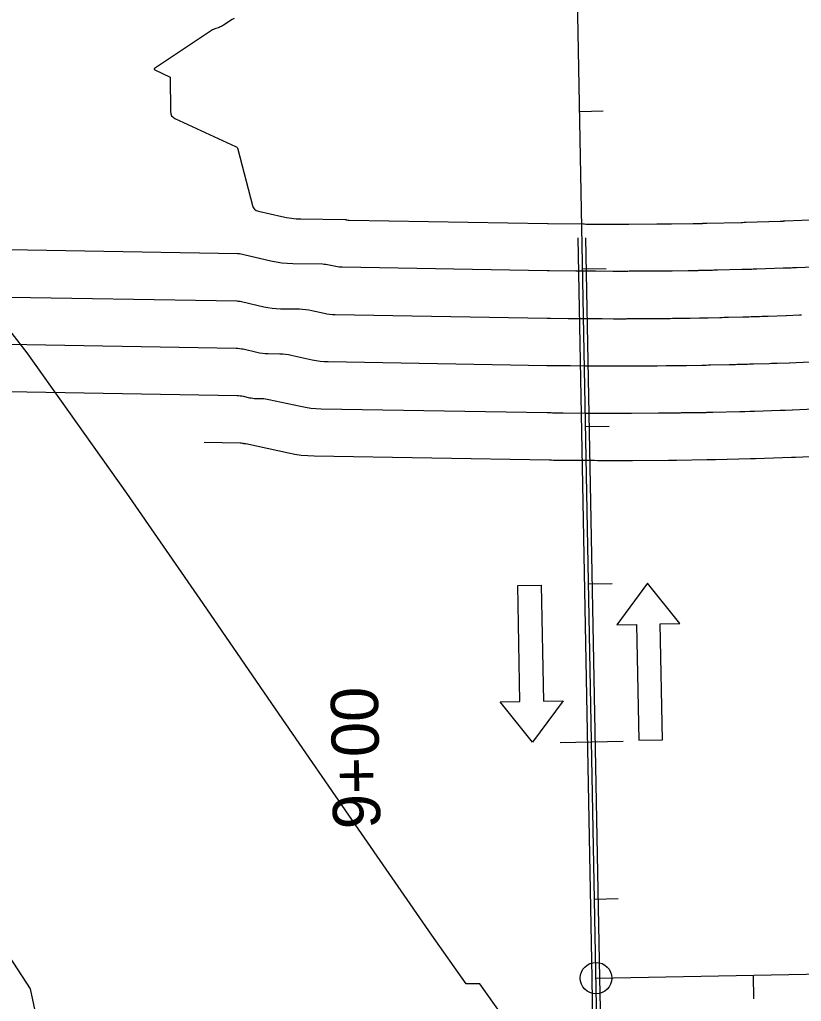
# Model space of a CAD drawing. Extents: x 1710723 to 1713003, y 548603 to 551142.
# Drawn here: x 1711666.3 to 1711765.6, y 549079.5 to 549204.1 of the extents above; entities that cross this region are included whole.
import ezdxf

# ---------------------------------------------------------------- set-up
doc = ezdxf.new("R2010")
doc.units = 0
for name, color, linetype in [('R_Contours', 7, 'Continuous'), ('R_Horz Alg', 7, 'Continuous'), ('R_Horz Alg Annot', 7, 'Continuous'), ('R_MOT', 7, 'Continuous'), ('R_No Plot', 7, 'Continuous'), ('R_Striping', 7, 'Continuous')]:
    doc.layers.add(name, color=color, linetype=linetype)

msp = doc.modelspace()

# ---------------------------------------------------------------- linework, layer by layer
at = {"layer": 'R_Contours'}
for points in [[(1711693.57, 549204.24), (1711693.33, 549204.11), (1711692.21, 549203.4), (1711692.08, 549203.32), (1711691.95, 549203.25), (1711691.81, 549203.19), (1711691.67, 549203.13), (1711691.1, 549202.93), (1711690.96, 549202.87), (1711690.82, 549202.81), (1711690.69, 549202.74), (1711690.56, 549202.66), (1711683.47, 549197.9), (1711683.42, 549197.85), (1711683.4, 549197.8), (1711683.42, 549197.76), (1711683.49, 549197.72), (1711685.43, 549196.82), (1711685.44, 549196.82), (1711685.44, 549196.82), (1711685.44, 549196.81), (1711685.44, 549196.81), (1711685.49, 549192.43), (1711685.53, 549192.15), (1711685.63, 549191.91), (1711685.81, 549191.71), (1711686.05, 549191.56), (1711693.75, 549188.02), (1711693.86, 549187.96), (1711693.94, 549187.88), (1711694, 549187.79), (1711694.04, 549187.68), (1711695.89, 549180.53), (1711696, 549180.26), (1711696.16, 549180.05), (1711696.37, 549179.9), (1711696.64, 549179.8), (1711699.63, 549179.11), (1711700.23, 549178.99), (1711700.83, 549178.9), (1711701.44, 549178.84), (1711702.05, 549178.82), (1711707.67, 549178.73), (1711707.71, 549178.72), (1711707.75, 549178.72), (1711707.8, 549178.72), (1711707.84, 549178.71), (1711708, 549178.67), (1711708.04, 549178.66), (1711708.08, 549178.66), (1711708.11, 549178.65), (1711708.15, 549178.65), (1711733.35, 549178.22), (1711733.38, 549178.22), (1711733.42, 549178.22), (1711737.9, 549178.17), (1711737.98, 549178.17), (1711738.06, 549178.17), (1711738.25, 549178.16), (1711738.28, 549178.16), (1711738.31, 549178.16), (1711738.33, 549178.16), (1711738.36, 549178.16), (1711738.5, 549178.16), (1711738.58, 549178.16), (1711741.56, 549178.15), (1711741.61, 549178.15), (1711741.71, 549178.15), (1711741.73, 549178.15), (1711743.14, 549178.15), (1711743.19, 549178.15), (1711743.23, 549178.15), (1711743.28, 549178.15), (1711743.32, 549178.15), (1711743.49, 549178.15), (1711743.58, 549178.15), (1711743.67, 549178.15), (1711747.21, 549178.18), (1711747.69, 549178.18), (1711748.16, 549178.18), (1711748.63, 549178.19), (1711749.1, 549178.2), (1711751.85, 549178.23), (1711751.92, 549178.23), (1711752, 549178.24), (1711752.16, 549178.24), (1711752.2, 549178.24), (1711752.24, 549178.24), (1711752.28, 549178.24), (1711752.32, 549178.24), (1711753, 549178.25), (1711753.07, 549178.26), (1711753.1, 549178.26), (1711753.37, 549178.26), (1711753.47, 549178.26), (1711753.57, 549178.27), (1711757.91, 549178.37), (1711757.96, 549178.37), (1711758.01, 549178.37), (1711758.06, 549178.37), (1711758.11, 549178.37), (1711758.31, 549178.38), (1711758.36, 549178.38), (1711758.41, 549178.39), (1711758.47, 549178.39), (1711758.52, 549178.39), (1711762.89, 549178.53), (1711762.95, 549178.53), (1711763.26, 549178.54), (1711763.31, 549178.55), (1711763.36, 549178.55), (1711763.42, 549178.55), (1711763.47, 549178.55), (1711767.77, 549178.73)], [(1711768.22, 549172.74), (1711764.95, 549172.61), (1711764.78, 549172.6), (1711764.62, 549172.6), (1711764.46, 549172.59), (1711764.29, 549172.58), (1711763.32, 549172.54), (1711763.27, 549172.54), (1711759.93, 549172.43), (1711759.77, 549172.43), (1711759.61, 549172.42), (1711759.45, 549172.42), (1711759.29, 549172.41), (1711758.66, 549172.39), (1711758.5, 549172.39), (1711758.34, 549172.38), (1711758.18, 549172.38), (1711758.02, 549172.37), (1711754.94, 549172.3), (1711754.78, 549172.3), (1711754.62, 549172.29), (1711754.47, 549172.29), (1711754.31, 549172.28), (1711753.41, 549172.26), (1711753.36, 549172.26), (1711753.3, 549172.26), (1711753.17, 549172.26), (1711753.09, 549172.26), (1711752.67, 549172.25), (1711752.59, 549172.25), (1711752.51, 549172.25), (1711752.43, 549172.24), (1711752.35, 549172.24), (1711751.73, 549172.23), (1711751.6, 549172.23), (1711751.47, 549172.23), (1711751.34, 549172.23), (1711751.21, 549172.23), (1711749.15, 549172.2), (1711748.77, 549172.19), (1711748.38, 549172.19), (1711747.99, 549172.18), (1711747.61, 549172.18), (1711744.94, 549172.16), (1711744.78, 549172.16), (1711744.63, 549172.16), (1711744.48, 549172.16), (1711744.32, 549172.16), (1711743.71, 549172.16), (1711743.56, 549172.15), (1711743.4, 549172.15), (1711743.25, 549172.15), (1711743.1, 549172.15), (1711742.25, 549172.15), (1711742.2, 549172.15), (1711742.15, 549172.15), (1711742.1, 549172.15), (1711742.05, 549172.15), (1711741.85, 549172.15), (1711741.8, 549172.15), (1711741.75, 549172.15), (1711741.7, 549172.15), (1711741.64, 549172.15), (1711739.43, 549172.16), (1711739.33, 549172.16), (1711739.23, 549172.16), (1711739.13, 549172.16), (1711739.03, 549172.16), (1711738.63, 549172.16), (1711738.53, 549172.16), (1711738.43, 549172.16), (1711738.33, 549172.17), (1711738.23, 549172.17), (1711737.53, 549172.17), (1711737.38, 549172.17), (1711737.23, 549172.18), (1711737.08, 549172.18), (1711736.93, 549172.18), (1711733.58, 549172.22), (1711733.52, 549172.22), (1711733.45, 549172.22), (1711733.39, 549172.22), (1711733.32, 549172.22), (1711707.27, 549172.67), (1711707.07, 549172.68), (1711706.88, 549172.7), (1711706.69, 549172.72), (1711706.49, 549172.76), (1711705.62, 549172.95), (1711705.41, 549172.99), (1711705.2, 549173.02), (1711704.99, 549173.04), (1711704.78, 549173.05), (1711701, 549173.11), (1711700.3, 549173.14), (1711699.61, 549173.21), (1711698.92, 549173.31), (1711698.23, 549173.45), (1711694.26, 549174.36), (1711694.2, 549174.38), (1711694.13, 549174.39), (1711694.06, 549174.39), (1711693.99, 549174.4), (1711662.46, 549174.94)], [(1711662.42, 549168.94), (1711693.91, 549168.4), (1711694.05, 549168.39), (1711694.2, 549168.38), (1711694.34, 549168.36), (1711694.48, 549168.33), (1711697.33, 549167.67), (1711697.85, 549167.57), (1711698.38, 549167.49), (1711698.91, 549167.44), (1711699.44, 549167.41), (1711701.88, 549167.38), (1711702.26, 549167.36), (1711702.65, 549167.32), (1711703.03, 549167.27), (1711703.41, 549167.2), (1711704.98, 549166.85), (1711705.33, 549166.78), (1711705.68, 549166.73), (1711706.03, 549166.7), (1711706.39, 549166.69), (1711733.29, 549166.22), (1711733.41, 549166.22), (1711733.52, 549166.22), (1711733.63, 549166.22), (1711733.74, 549166.22), (1711735.97, 549166.19), (1711736.22, 549166.19), (1711736.48, 549166.18), (1711736.74, 549166.18), (1711737, 549166.18), (1711738.2, 549166.17), (1711738.37, 549166.17), (1711738.55, 549166.17), (1711738.72, 549166.16), (1711738.89, 549166.16), (1711739.59, 549166.16), (1711739.76, 549166.16), (1711739.93, 549166.16), (1711740.1, 549166.16), (1711740.28, 549166.16), (1711741.73, 549166.15), (1711741.81, 549166.15), (1711741.9, 549166.15), (1711741.99, 549166.15), (1711742.07, 549166.15), (1711742.42, 549166.15), (1711742.51, 549166.15), (1711742.6, 549166.15), (1711742.68, 549166.15), (1711742.77, 549166.15), (1711743.33, 549166.15), (1711743.45, 549166.16), (1711743.57, 549166.16), (1711743.7, 549166.16), (1711743.82, 549166.16), (1711745.15, 549166.17), (1711745.41, 549166.17), (1711745.68, 549166.17), (1711745.94, 549166.17), (1711746.2, 549166.17), (1711748, 549166.19), (1711748.3, 549166.19), (1711748.6, 549166.19), (1711748.9, 549166.19), (1711749.21, 549166.2), (1711750.57, 549166.22), (1711750.79, 549166.22), (1711751.01, 549166.22), (1711751.23, 549166.23), (1711751.45, 549166.23), (1711752.65, 549166.25), (1711752.71, 549166.25), (1711752.78, 549166.25), (1711752.84, 549166.25), (1711752.9, 549166.25), (1711753.18, 549166.26), (1711753.27, 549166.26), (1711753.36, 549166.26), (1711753.54, 549166.26), (1711753.59, 549166.27), (1711753.63, 549166.27), (1711753.68, 549166.27), (1711753.72, 549166.27), (1711755.24, 549166.31), (1711755.51, 549166.31), (1711755.78, 549166.32), (1711756.04, 549166.33), (1711756.31, 549166.33), (1711758.13, 549166.38), (1711758.4, 549166.38), (1711758.66, 549166.39), (1711758.93, 549166.4), (1711759.2, 549166.41), (1711760.27, 549166.44), (1711760.54, 549166.45), (1711760.81, 549166.46), (1711761.08, 549166.47), (1711761.35, 549166.48), (1711763.65, 549166.55), (1711763.7, 549166.55), (1711765.33, 549166.62), (1711765.6, 549166.63)], [(1711662.38, 549162.94), (1711693.83, 549162.4), (1711694.05, 549162.39), (1711694.26, 549162.37), (1711694.48, 549162.34), (1711694.69, 549162.3), (1711696.43, 549161.9), (1711696.79, 549161.82), (1711697.15, 549161.77), (1711697.52, 549161.73), (1711697.88, 549161.72), (1711699.36, 549161.69), (1711699.73, 549161.68), (1711700.1, 549161.65), (1711700.46, 549161.59), (1711700.82, 549161.52), (1711703.48, 549160.94), (1711703.98, 549160.84), (1711704.48, 549160.77), (1711704.99, 549160.72), (1711705.5, 549160.7), (1711733.27, 549160.22), (1711733.43, 549160.22), (1711733.59, 549160.22), (1711733.75, 549160.22), (1711733.91, 549160.21), (1711735.2, 549160.2), (1711735.47, 549160.2), (1711735.73, 549160.19), (1711736, 549160.19), (1711736.27, 549160.19), (1711738.17, 549160.17), (1711738.42, 549160.17), (1711738.66, 549160.17), (1711738.91, 549160.16), (1711739.16, 549160.16), (1711740.28, 549160.16), (1711740.46, 549160.16), (1711740.63, 549160.16), (1711740.81, 549160.16), (1711740.99, 549160.16), (1711741.81, 549160.16), (1711741.93, 549160.16), (1711742.05, 549160.16), (1711742.18, 549160.16), (1711742.3, 549160.16), (1711742.87, 549160.16), (1711742.95, 549160.16), (1711743.04, 549160.16), (1711743.13, 549160.16), (1711743.22, 549160.16), (1711743.57, 549160.16), (1711743.66, 549160.16), (1711743.75, 549160.16), (1711743.83, 549160.16), (1711743.92, 549160.16), (1711746.2, 549160.18), (1711746.46, 549160.18), (1711746.73, 549160.18), (1711746.99, 549160.18), (1711747.25, 549160.18), (1711748.39, 549160.19), (1711748.61, 549160.19), (1711748.83, 549160.19), (1711749.04, 549160.2), (1711749.26, 549160.2), (1711750.13, 549160.21), (1711750.34, 549160.21), (1711750.56, 549160.22), (1711750.77, 549160.22), (1711750.99, 549160.22), (1711752.95, 549160.25), (1711753, 549160.26), (1711753.04, 549160.26), (1711753.09, 549160.26), (1711753.13, 549160.26), (1711753.31, 549160.26), (1711753.4, 549160.26), (1711753.49, 549160.26), (1711753.78, 549160.27), (1711753.85, 549160.27), (1711753.91, 549160.27), (1711753.97, 549160.27), (1711754.04, 549160.28), (1711756.41, 549160.34), (1711756.67, 549160.34), (1711756.93, 549160.35), (1711757.19, 549160.35), (1711757.44, 549160.36), (1711758.48, 549160.38), (1711758.73, 549160.39), (1711758.99, 549160.4), (1711759.25, 549160.41), (1711759.51, 549160.41), (1711761.5, 549160.48), (1711761.76, 549160.49), (1711762.01, 549160.5), (1711762.26, 549160.51), (1711762.51, 549160.51), (1711764.03, 549160.56), (1711764.08, 549160.56), (1711766.63, 549160.67)], [(1711662.34, 549156.95), (1711693.93, 549156.4), (1711694.13, 549156.39), (1711694.33, 549156.37), (1711694.53, 549156.34), (1711694.73, 549156.3), (1711695.52, 549156.12), (1711695.72, 549156.08), (1711695.92, 549156.05), (1711696.12, 549156.03), (1711696.33, 549156.02), (1711697.14, 549156.01), (1711697.34, 549156), (1711697.55, 549155.98), (1711697.75, 549155.95), (1711697.95, 549155.91), (1711701.97, 549155.03), (1711702.62, 549154.9), (1711703.29, 549154.81), (1711703.95, 549154.75), (1711704.62, 549154.72), (1711733.32, 549154.22), (1711733.49, 549154.22), (1711733.65, 549154.22), (1711733.82, 549154.22), (1711733.99, 549154.21), (1711734.65, 549154.21), (1711734.82, 549154.2), (1711734.99, 549154.2), (1711735.15, 549154.2), (1711735.32, 549154.2), (1711738.15, 549154.17), (1711738.47, 549154.17), (1711738.78, 549154.17), (1711739.1, 549154.17), (1711739.42, 549154.16), (1711741.12, 549154.16), (1711741.23, 549154.16), (1711741.34, 549154.16), (1711741.45, 549154.16), (1711741.55, 549154.16), (1711741.99, 549154.16), (1711742.1, 549154.16), (1711742.21, 549154.16), (1711742.32, 549154.16), (1711742.43, 549154.16), (1711743.38, 549154.16), (1711743.43, 549154.16), (1711743.49, 549154.16), (1711743.54, 549154.16), (1711743.59, 549154.16), (1711743.81, 549154.16), (1711743.86, 549154.16), (1711743.92, 549154.16), (1711743.97, 549154.16), (1711744.02, 549154.16), (1711747.45, 549154.19), (1711747.61, 549154.19), (1711747.77, 549154.19), (1711747.93, 549154.19), (1711748.09, 549154.19), (1711748.79, 549154.19), (1711748.92, 549154.2), (1711749.05, 549154.2), (1711749.18, 549154.2), (1711749.31, 549154.2), (1711749.84, 549154.21), (1711749.97, 549154.21), (1711750.1, 549154.21), (1711750.23, 549154.21), (1711750.37, 549154.22), (1711753.26, 549154.26), (1711753.31, 549154.26), (1711753.36, 549154.26), (1711753.5, 549154.26), (1711753.58, 549154.27), (1711754.02, 549154.27), (1711754.1, 549154.28), (1711754.18, 549154.28), (1711754.27, 549154.28), (1711754.35, 549154.28), (1711757.77, 549154.37), (1711757.92, 549154.37), (1711758.08, 549154.38), (1711758.23, 549154.38), (1711758.39, 549154.38), (1711759.01, 549154.4), (1711759.16, 549154.4), (1711759.32, 549154.41), (1711759.47, 549154.41), (1711759.63, 549154.42), (1711762.9, 549154.53), (1711763.06, 549154.53), (1711763.21, 549154.54), (1711763.36, 549154.54), (1711763.51, 549154.55), (1711764.4, 549154.57), (1711764.42, 549154.57), (1711764.46, 549154.58), (1711768.09, 549154.73)], [(1711689.77, 549150.47), (1711694.32, 549150.4), (1711694.36, 549150.39), (1711694.4, 549150.39), (1711694.44, 549150.38), (1711694.47, 549150.38), (1711694.62, 549150.34), (1711694.66, 549150.34), (1711694.7, 549150.33), (1711694.73, 549150.33), (1711694.77, 549150.32), (1711694.92, 549150.32), (1711694.96, 549150.32), (1711695, 549150.32), (1711695.03, 549150.31), (1711695.07, 549150.31), (1711700.46, 549149.12), (1711701.27, 549148.96), (1711702.09, 549148.84), (1711702.91, 549148.77), (1711703.74, 549148.73), (1711733.59, 549148.22), (1711733.66, 549148.22), (1711733.72, 549148.22), (1711733.79, 549148.22), (1711733.85, 549148.22), (1711734.11, 549148.21), (1711734.17, 549148.21), (1711734.24, 549148.21), (1711734.3, 549148.21), (1711734.37, 549148.21), (1711738.12, 549148.17), (1711738.51, 549148.17), (1711738.9, 549148.17), (1711739.3, 549148.17), (1711739.69, 549148.16), (1711741.96, 549148.16), (1711742.04, 549148.16), (1711742.12, 549148.16), (1711742.28, 549148.16), (1711742.32, 549148.16), (1711742.36, 549148.16), (1711742.4, 549148.16), (1711742.44, 549148.16), (1711743.89, 549148.16), (1711743.97, 549148.16), (1711744.05, 549148.16), (1711744.09, 549148.16), (1711744.13, 549148.16), (1711748.71, 549148.2), (1711748.76, 549148.2), (1711748.82, 549148.2), (1711748.88, 549148.2), (1711748.93, 549148.2), (1711749.18, 549148.2), (1711749.23, 549148.2), (1711749.27, 549148.2), (1711749.32, 549148.2), (1711749.37, 549148.2), (1711749.55, 549148.2), (1711749.65, 549148.2), (1711749.74, 549148.21), (1711753.56, 549148.27), (1711753.59, 549148.27), (1711753.67, 549148.27), (1711754.26, 549148.28), (1711754.36, 549148.28), (1711754.46, 549148.28), (1711754.56, 549148.29), (1711754.66, 549148.29), (1711759.13, 549148.4), (1711759.18, 549148.4), (1711759.23, 549148.4), (1711759.28, 549148.4), (1711759.34, 549148.41), (1711759.54, 549148.41), (1711759.6, 549148.41), (1711759.65, 549148.41), (1711759.7, 549148.41), (1711759.75, 549148.42), (1711764.31, 549148.57), (1711764.4, 549148.57), (1711764.5, 549148.58), (1711764.78, 549148.59), (1711764.8, 549148.59), (1711764.83, 549148.59), (1711769.56, 549148.79)]]:
    msp.add_lwpolyline(points, dxfattribs=at)
at = {"layer": 'R_Horz Alg'}
for p, q in [((1711741.76, 548962.46), (1711737.05, 549212.41)), ((1711739.5, 549082.44), (1711789.16, 549083.37))]:
    msp.add_line(p, q, dxfattribs=at)
at = {"layer": 'R_Horz Alg Annot'}
for points in [[(1711740.43, 549192.47), (1711737.43, 549192.42)], [(1711740.81, 549172.48), (1711737.81, 549172.42)], [(1711741.18, 549152.48), (1711738.18, 549152.43)], [(1711741.56, 549132.49), (1711738.56, 549132.43)], [(1711734.94, 549112.36), (1711742.94, 549112.51)], [(1711742.31, 549092.49), (1711739.31, 549092.44)], [(1711759.55, 549079.82), (1711759.5, 549082.81)]]:
    msp.add_lwpolyline(points, dxfattribs=at)
msp.add_circle((1711739.5, 549082.44), 2, dxfattribs=at)
at = {"layer": 'R_MOT'}
for points in [[(1711808.51, 549014.46), (1711797.83, 549015.34), (1711780.72, 549024.22), (1711764.61, 549034.78), (1711754.93, 549047.27), (1711743.56, 549057.03), (1711737.29, 549064.07), (1711724.77, 549081.73), (1711723.01, 549081.72), (1711718.65, 549087.89), (1711708.97, 549101.92), (1711699.3, 549115.95), (1711689.62, 549129.98), (1711679.95, 549144.01), (1711667.27, 549161.8), (1711663.44, 549166.72)], [(1711633.24, 549130.45), (1711648.31, 549110.73), (1711654.76, 549100.85), (1711661.21, 549090.97), (1711667.66, 549081.09), (1711669.8, 549071.12), (1711670.82, 549061.14), (1711671.85, 549051.16), (1711672.88, 549041.18), (1711673.91, 549031.19), (1711688.03, 549012.49)]]:
    msp.add_lwpolyline(points, dxfattribs=at)
for points in [[(1711735.34, 549117.65), (1711731.44, 549112.39), (1711727.34, 549117.5), (1711729.84, 549117.55), (1711729.56, 549132.26), (1711732.56, 549132.32), (1711732.84, 549117.61)], [(1711750.16, 549127.45), (1711746.06, 549132.57), (1711742.16, 549127.3), (1711744.66, 549127.35), (1711744.93, 549112.64), (1711747.93, 549112.7), (1711747.66, 549127.41)]]:
    msp.add_lwpolyline(points, close=True, dxfattribs=at)
at = {"layer": 'R_No Plot'}
msp.add_lwpolyline([(1711869.98, 549020.25), (1711864.58, 549010.42), (1711860.69, 549005.72), (1711855.6, 549004.99), (1711831.16, 549007.62), (1711823.52, 549009.4), (1711808.51, 549014.46), (1711797.83, 549015.34), (1711780.72, 549024.22), (1711764.61, 549034.78), (1711754.93, 549047.27), (1711743.56, 549057.03), (1711737.29, 549064.07), (1711724.77, 549081.73), (1711723.01, 549081.72), (1711718.65, 549087.89), (1711708.97, 549101.92), (1711699.3, 549115.95), (1711689.62, 549129.98), (1711679.95, 549144.01), (1711667.27, 549161.8), (1711663.44, 549166.72)], dxfattribs=at)
at = {"layer": 'R_Striping'}
for p, q in [((1711739, 549082.43), (1711737.23, 549176.42)), ((1711740, 549082.45), (1711738.23, 549176.43)), ((1711739.6, 549050.42), (1711739, 549082.43)), ((1711740.6, 549050.44), (1711740, 549082.45))]:
    msp.add_line(p, q, dxfattribs=at)

# ---------------------------------------------------------------- texts
at = {"layer": 'R_Horz Alg Annot'}
msp.add_text('9+00', height=6, rotation=91.0787, dxfattribs=at).set_placement((1711712.14, 549101.41))

doc.saveas('drawing.dxf')
